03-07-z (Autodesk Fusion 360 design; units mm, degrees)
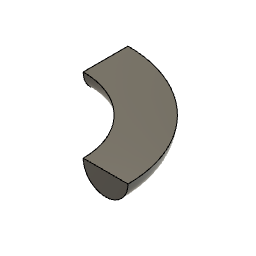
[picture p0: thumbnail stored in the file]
box_primitive "直方体プリミティブ" DistanceX 50 DistanceY 50 DistanceZ 30 OffsetDistanceX 0 OffsetDistanceY 0
step "トーラス プリミティブ" MinorDiameter 15 MajorDiameter 80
